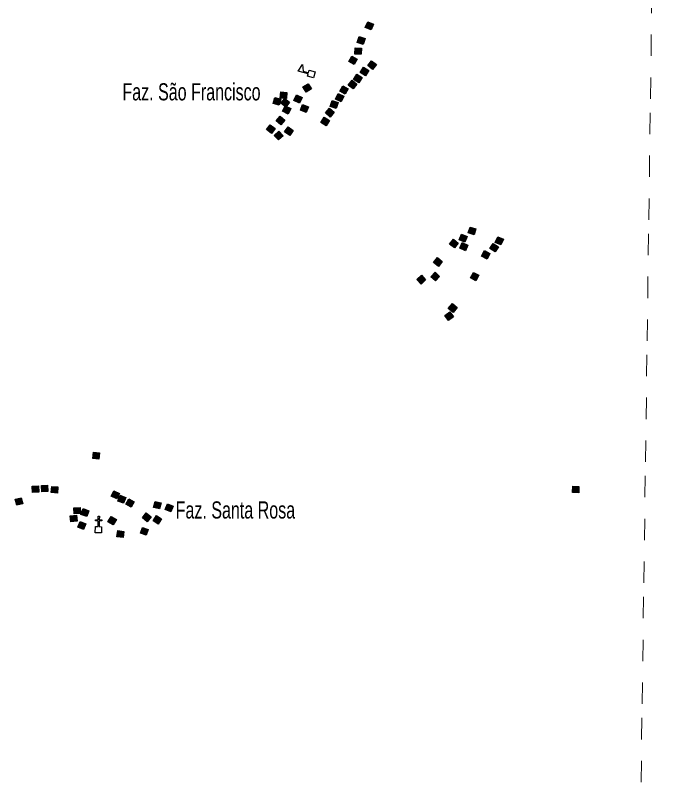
# Model space of a CAD drawing. Extents: x 679 to 705, y 7427.4 to 7455.4.
# Drawn here: x 701.873 to 704.9, y 7439.999 to 7443.572 of the extents above; entities that cross this region are included whole.
import ezdxf

# ---------------------------------------------------------------- set-up
doc = ezdxf.new("R2010")
doc.units = 0
doc.header["$LTSCALE"] = 0.032
doc.linetypes.add('SHORT_DASHED', pattern=[2.7, 1.5, -1.2])
for name, color, linetype, lineweight in [('2', 7, 'Continuous', 25), ('4', 7, 'Continuous', 25), ('58', 7, 'SHORT_DASHED', 13), ('6', 7, 'Continuous', 25)]:
    doc.layers.add(name, color=color, linetype=linetype, lineweight=lineweight)
doc.layers.add('61', color=7, linetype='Continuous')

msp = doc.modelspace()

# ---------------------------------------------------------------- hatches: boundary and pattern name
at = {"layer": '2'}
for points in [[(703.5186, 7443.5423), (703.5452, 7443.5308), (703.5337, 7443.5042), (703.5071, 7443.5157)], [(703.4791, 7443.4731), (703.5064, 7443.4636), (703.4969, 7443.4362), (703.4695, 7443.4457)], [(703.46, 7443.4203), (703.4889, 7443.4193), (703.4879, 7443.3903), (703.4589, 7443.3913)], [(703.4445, 7443.382), (703.4694, 7443.367), (703.4544, 7443.3422), (703.4295, 7443.3572)], [(703.5366, 7443.3602), (703.559, 7443.3417), (703.5405, 7443.3193), (703.5182, 7443.3378)], [(703.4993, 7443.3295), (703.5237, 7443.3137), (703.5079, 7443.2894), (703.4836, 7443.3051)], [(703.4671, 7443.2975), (703.4917, 7443.2822), (703.4764, 7443.2576), (703.4518, 7443.2729)], [(703.2399, 7443.2529), (703.2552, 7443.2283), (703.2306, 7443.213), (703.2153, 7443.2376)], [(703.4023, 7443.243), (703.4277, 7443.229), (703.4137, 7443.2036), (703.3883, 7443.2176)], [(703.4451, 7443.2692), (703.4681, 7443.2514), (703.4503, 7443.2285), (703.4274, 7443.2462)], [(703.1124, 7443.2148), (703.1414, 7443.2124), (703.139, 7443.1835), (703.1101, 7443.1858)], [(703.3797, 7443.2071), (703.4061, 7443.1951), (703.3941, 7443.1687), (703.3677, 7443.1807)], [(703.0852, 7443.1882), (703.1131, 7443.1804), (703.1053, 7443.1525), (703.0774, 7443.1603)], [(703.1307, 7443.1843), (703.1534, 7443.1662), (703.1354, 7443.1436), (703.1127, 7443.1616)], [(703.1852, 7443.2007), (703.2116, 7443.1886), (703.1994, 7443.1622), (703.1731, 7443.1744)], [(703.3524, 7443.1744), (703.3799, 7443.165), (703.3705, 7443.1375), (703.343, 7443.147)], [(703.1332, 7443.1499), (703.1591, 7443.1369), (703.1461, 7443.111), (703.1202, 7443.1239)], [(703.2145, 7443.1556), (703.2415, 7443.145), (703.2309, 7443.118), (703.2039, 7443.1286)], [(703.3403, 7443.1381), (703.3623, 7443.1193), (703.3435, 7443.0972), (703.3214, 7443.1161)], [(703.1088, 7443.1014), (703.1311, 7443.0829), (703.1127, 7443.0606), (703.0903, 7443.079)], [(703.3154, 7443.0962), (703.3398, 7443.0805), (703.324, 7443.0561), (703.2997, 7443.0719)], [(703.0634, 7443.0614), (703.0864, 7443.0438), (703.0688, 7443.0208), (703.0458, 7443.0383)], [(703.1032, 7443.0313), (703.1231, 7443.0102), (703.1019, 7442.9903), (703.0821, 7443.0114)], [(703.1471, 7443.0517), (703.1709, 7443.0351), (703.1542, 7443.0113), (703.1305, 7443.0279)], [(703.9959, 7442.5837), (704.0237, 7442.5755), (704.0155, 7442.5476), (703.9877, 7442.5559)], [(703.9184, 7442.527), (703.9411, 7442.509), (703.9231, 7442.4862), (703.9004, 7442.5042)], [(703.9561, 7442.551), (703.983, 7442.5402), (703.9722, 7442.5133), (703.9453, 7442.5241)], [(704.126, 7442.5386), (704.1523, 7442.5264), (704.1402, 7442.5001), (704.1138, 7442.5123)], [(703.9597, 7442.5113), (703.9864, 7442.4998), (703.9748, 7442.4732), (703.9482, 7442.4847)], [(704.1047, 7442.5075), (704.1291, 7442.4918), (704.1133, 7442.4674), (704.089, 7442.4831)], [(704.0632, 7442.4735), (704.0888, 7442.46), (704.0753, 7442.4344), (704.0497, 7442.4479)], [(703.8434, 7442.4408), (703.8662, 7442.4228), (703.8482, 7442.4001), (703.8254, 7442.4181)], [(703.7687, 7442.3587), (703.7887, 7442.3377), (703.7678, 7442.3177), (703.7477, 7442.3387)], [(703.8329, 7442.3731), (703.8542, 7442.3533), (703.8344, 7442.3321), (703.8132, 7442.3518)], [(704.0116, 7442.3722), (704.037, 7442.3583), (704.023, 7442.3328), (703.9976, 7442.3468)], [(703.9134, 7442.2262), (703.9355, 7442.2074), (703.9167, 7442.1853), (703.8946, 7442.2042)], [(703.9019, 7442.1878), (703.9191, 7442.1645), (703.8958, 7442.1473), (703.8786, 7442.1706)], [(702.2667, 7441.5293), (702.2632, 7441.5005), (702.2344, 7441.5039), (702.2379, 7441.5327)], [(701.9804, 7441.3754), (701.9822, 7441.3465), (701.9532, 7441.3447), (701.9515, 7441.3737)], [(702.0238, 7441.3783), (702.0249, 7441.3493), (701.9959, 7441.3482), (701.9948, 7441.3772)], [(702.0717, 7441.3703), (702.0693, 7441.3414), (702.0404, 7441.3438), (702.0428, 7441.3727)], [(702.3591, 7441.3404), (702.3465, 7441.3143), (702.3204, 7441.3268), (702.3329, 7441.353)], [(704.5045, 7441.3727), (704.5038, 7441.3437), (704.4748, 7441.3444), (704.4755, 7441.3734)], [(701.9008, 7441.3203), (701.9081, 7441.2922), (701.88, 7441.2849), (701.8728, 7441.313)], [(702.3887, 7441.3213), (702.3786, 7441.2942), (702.3514, 7441.3042), (702.3615, 7441.3314)], [(702.4279, 7441.3012), (702.4141, 7441.2757), (702.3886, 7441.2895), (702.4024, 7441.3151)], [(702.5536, 7441.296), (702.5463, 7441.2679), (702.5182, 7441.2751), (702.5255, 7441.3032)], [(702.6106, 7441.2808), (702.5995, 7441.254), (702.5727, 7441.2651), (702.5839, 7441.2919)], [(702.1752, 7441.2748), (702.1765, 7441.2459), (702.1475, 7441.2446), (702.1462, 7441.2736)], [(702.2166, 7441.2589), (702.2062, 7441.2318), (702.1791, 7441.2422), (702.1895, 7441.2693)], [(702.5068, 7441.2307), (702.4885, 7441.2082), (702.466, 7441.2266), (702.4844, 7441.249)], [(702.1582, 7441.239), (702.1615, 7441.2102), (702.1327, 7441.2069), (702.1294, 7441.2357)], [(702.2025, 7441.198), (702.1911, 7441.1714), (702.1644, 7441.1828), (702.1759, 7441.2095)], [(702.3453, 7441.2177), (702.3302, 7441.193), (702.3054, 7441.2081), (702.3206, 7441.2329)], [(702.5559, 7441.2218), (702.5403, 7441.1973), (702.5158, 7441.2128), (702.5314, 7441.2373)], [(702.4936, 7441.1724), (702.4845, 7441.1449), (702.457, 7441.154), (702.4661, 7441.1815)], [(702.3802, 7441.1624), (702.3759, 7441.1338), (702.3472, 7441.1381), (702.3515, 7441.1667)]]:
    msp.add_hatch(color=256, dxfattribs=at).paths.add_polyline_path(points)

# ---------------------------------------------------------------- linework, layer by layer
for points in [[(703.5186, 7443.5423), (703.5452, 7443.5308), (703.5337, 7443.5042), (703.5071, 7443.5157)], [(703.4791, 7443.4731), (703.5064, 7443.4636), (703.4969, 7443.4362), (703.4695, 7443.4457)], [(703.46, 7443.4203), (703.4889, 7443.4193), (703.4879, 7443.3903), (703.4589, 7443.3913)], [(703.4445, 7443.382), (703.4694, 7443.367), (703.4544, 7443.3422), (703.4295, 7443.3572)], [(703.5366, 7443.3602), (703.559, 7443.3417), (703.5405, 7443.3193), (703.5182, 7443.3378)], [(703.4993, 7443.3295), (703.5237, 7443.3137), (703.5079, 7443.2894), (703.4836, 7443.3051)], [(703.4671, 7443.2975), (703.4917, 7443.2822), (703.4764, 7443.2576), (703.4518, 7443.2729)], [(703.2399, 7443.2529), (703.2552, 7443.2283), (703.2306, 7443.213), (703.2153, 7443.2376)], [(703.4023, 7443.243), (703.4277, 7443.229), (703.4137, 7443.2036), (703.3883, 7443.2176)], [(703.4451, 7443.2692), (703.4681, 7443.2514), (703.4503, 7443.2285), (703.4274, 7443.2462)], [(703.1124, 7443.2148), (703.1414, 7443.2124), (703.139, 7443.1835), (703.1101, 7443.1858)], [(703.3797, 7443.2071), (703.4061, 7443.1951), (703.3941, 7443.1687), (703.3677, 7443.1807)], [(703.0852, 7443.1882), (703.1131, 7443.1804), (703.1053, 7443.1525), (703.0774, 7443.1603)], [(703.1307, 7443.1843), (703.1534, 7443.1662), (703.1354, 7443.1436), (703.1127, 7443.1616)], [(703.1852, 7443.2007), (703.2116, 7443.1886), (703.1994, 7443.1622), (703.1731, 7443.1744)], [(703.3524, 7443.1744), (703.3799, 7443.165), (703.3705, 7443.1375), (703.343, 7443.147)], [(703.1332, 7443.1499), (703.1591, 7443.1369), (703.1461, 7443.111), (703.1202, 7443.1239)], [(703.2145, 7443.1556), (703.2415, 7443.145), (703.2309, 7443.118), (703.2039, 7443.1286)], [(703.3403, 7443.1381), (703.3623, 7443.1193), (703.3435, 7443.0972), (703.3214, 7443.1161)], [(703.1088, 7443.1014), (703.1311, 7443.0829), (703.1127, 7443.0606), (703.0903, 7443.079)], [(703.3154, 7443.0962), (703.3398, 7443.0805), (703.324, 7443.0561), (703.2997, 7443.0719)], [(703.0634, 7443.0614), (703.0864, 7443.0438), (703.0688, 7443.0208), (703.0458, 7443.0383)], [(703.1032, 7443.0313), (703.1231, 7443.0102), (703.1019, 7442.9903), (703.0821, 7443.0114)], [(703.1471, 7443.0517), (703.1709, 7443.0351), (703.1542, 7443.0113), (703.1305, 7443.0279)], [(703.9959, 7442.5837), (704.0237, 7442.5755), (704.0155, 7442.5476), (703.9877, 7442.5559)], [(703.9184, 7442.527), (703.9411, 7442.509), (703.9231, 7442.4862), (703.9004, 7442.5042)], [(703.9561, 7442.551), (703.983, 7442.5402), (703.9722, 7442.5133), (703.9453, 7442.5241)], [(704.126, 7442.5386), (704.1523, 7442.5264), (704.1402, 7442.5001), (704.1138, 7442.5123)], [(703.9597, 7442.5113), (703.9864, 7442.4998), (703.9748, 7442.4732), (703.9482, 7442.4847)], [(704.1047, 7442.5075), (704.1291, 7442.4918), (704.1133, 7442.4674), (704.089, 7442.4831)], [(704.0632, 7442.4735), (704.0888, 7442.46), (704.0753, 7442.4344), (704.0497, 7442.4479)], [(703.8434, 7442.4408), (703.8662, 7442.4228), (703.8482, 7442.4001), (703.8254, 7442.4181)], [(703.7687, 7442.3587), (703.7887, 7442.3377), (703.7678, 7442.3177), (703.7477, 7442.3387)], [(703.8329, 7442.3731), (703.8542, 7442.3533), (703.8344, 7442.3321), (703.8132, 7442.3518)], [(704.0116, 7442.3722), (704.037, 7442.3583), (704.023, 7442.3328), (703.9976, 7442.3468)], [(703.9134, 7442.2262), (703.9355, 7442.2074), (703.9167, 7442.1853), (703.8946, 7442.2042)], [(703.9019, 7442.1878), (703.9191, 7442.1645), (703.8958, 7442.1473), (703.8786, 7442.1706)], [(702.2667, 7441.5293), (702.2632, 7441.5005), (702.2344, 7441.5039), (702.2379, 7441.5327)], [(701.9804, 7441.3754), (701.9822, 7441.3465), (701.9532, 7441.3447), (701.9515, 7441.3737)], [(702.0238, 7441.3783), (702.0249, 7441.3493), (701.9959, 7441.3482), (701.9948, 7441.3772)], [(702.0717, 7441.3703), (702.0693, 7441.3414), (702.0404, 7441.3438), (702.0428, 7441.3727)], [(702.3591, 7441.3404), (702.3465, 7441.3143), (702.3204, 7441.3268), (702.3329, 7441.353)], [(704.5045, 7441.3727), (704.5038, 7441.3437), (704.4748, 7441.3444), (704.4755, 7441.3734)], [(701.9008, 7441.3203), (701.9081, 7441.2922), (701.88, 7441.2849), (701.8728, 7441.313)], [(702.3887, 7441.3213), (702.3786, 7441.2942), (702.3514, 7441.3042), (702.3615, 7441.3314)], [(702.4279, 7441.3012), (702.4141, 7441.2757), (702.3886, 7441.2895), (702.4024, 7441.3151)], [(702.5536, 7441.296), (702.5463, 7441.2679), (702.5182, 7441.2751), (702.5255, 7441.3032)], [(702.6106, 7441.2808), (702.5995, 7441.254), (702.5727, 7441.2651), (702.5839, 7441.2919)], [(702.1752, 7441.2748), (702.1765, 7441.2459), (702.1475, 7441.2446), (702.1462, 7441.2736)], [(702.2166, 7441.2589), (702.2062, 7441.2318), (702.1791, 7441.2422), (702.1895, 7441.2693)], [(702.5068, 7441.2307), (702.4885, 7441.2082), (702.466, 7441.2266), (702.4844, 7441.249)], [(702.1582, 7441.239), (702.1615, 7441.2102), (702.1327, 7441.2069), (702.1294, 7441.2357)], [(702.2025, 7441.198), (702.1911, 7441.1714), (702.1644, 7441.1828), (702.1759, 7441.2095)], [(702.3453, 7441.2177), (702.3302, 7441.193), (702.3054, 7441.2081), (702.3206, 7441.2329)], [(702.5559, 7441.2218), (702.5403, 7441.1973), (702.5158, 7441.2128), (702.5314, 7441.2373)], [(702.4936, 7441.1724), (702.4845, 7441.1449), (702.457, 7441.154), (702.4661, 7441.1815)], [(702.3802, 7441.1624), (702.3759, 7441.1338), (702.3472, 7441.1381), (702.3515, 7441.1667)]]:
    msp.add_lwpolyline(points, close=True, dxfattribs=at)
at = {"layer": '4'}
for points in [[(703.2407, 7443.2995), (703.1939, 7443.3118), (703.2137, 7443.3417), (703.2167, 7443.3109), (703.2419, 7443.3043)], [(703.2419, 7443.3043), (703.245, 7443.316), (703.2731, 7443.3086), (703.2657, 7443.2805), (703.2376, 7443.2879), (703.2407, 7443.2995)]]:
    msp.add_lwpolyline(points, dxfattribs=at)
at = {"layer": '58'}
msp.add_lwpolyline([(704.7919, 7439.7922), (704.7996, 7440.3572), (704.8074, 7440.9223), (704.8151, 7441.4873), (704.8229, 7442.0524), (704.8306, 7442.6174), (704.8384, 7443.1825), (704.8461, 7443.7476), (704.8539, 7444.3126), (704.8616, 7444.8777), (704.8693, 7445.4427), (704.8771, 7446.0078), (704.8848, 7446.5728), (704.8925, 7447.1379), (704.9003, 7447.7029)], dxfattribs=at)
at = {"layer": '6'}
for points in [[(702.2591, 7441.1852), (702.2598, 7441.2123), (702.2477, 7441.2127), (702.2479, 7441.2176), (702.26, 7441.2172), (702.2604, 7441.2336), (702.2652, 7441.2335), (702.2648, 7441.2171), (702.2769, 7441.2168), (702.2767, 7441.2119), (702.2646, 7441.2122), (702.2639, 7441.1851)], [(702.2639, 7441.1851), (702.276, 7441.1848), (702.2752, 7441.1558), (702.2462, 7441.1566), (702.247, 7441.1856), (702.2591, 7441.1852)]]:
    msp.add_lwpolyline(points, dxfattribs=at)

# ---------------------------------------------------------------- texts
at = {"layer": '61', "width": 0.7}
for s, p in [('Faz. São Francisco', (702.3729, 7443.1749)), ('Faz. Santa Rosa', (702.6216, 7441.223))]:
    msp.add_text(s, height=0.08, dxfattribs=at).set_placement(p)

doc.saveas('drawing.dxf')
